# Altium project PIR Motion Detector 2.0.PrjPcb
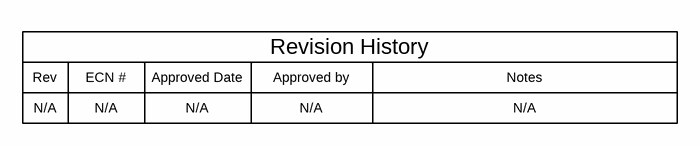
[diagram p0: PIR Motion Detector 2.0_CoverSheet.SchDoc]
CopyrightYear: 2016; PCB_Layout: Krypton Solutions; PCB_Rev: E1; PRJ_Customer: Public Release; PRJ_Engineer: Bilal Malik; PRJ_Number: TIDA-01069; PRJ_Title: Adv Motion Detector Using PIR Sensors; SCH_Rev: E1; TechSupport: http://www.ti.com/support; TID: 01069
4 sheets, 139 parts. Net scope: global (net labels, ports and power ports of the same name join across sheets).
Board file: PIR Motion Detector 2.0_PCB.PcbDoc
Sheets:
  PIR Motion Detector 2.0_CoverSheet.SchDoc
  PIR Motion Detector 2.0_BlankSheet.SchDoc
  PIR Motion Detector 2.0_PowerSheet.SchDoc
  PIR Motion Detector 2.0_EVM_Hardware.SchDoc

## Sheet PIR Motion Detector 2.0_CoverSheet.SchDoc: Cover Sheet
size 431 x 279 mm; Date: Not shown in title block; ApprovedBy: Not shown in title block; CheckedBy: Not shown in title block; Author: Not shown in title block; CompanyName: Not shown in title block; DrawnBy: Bilal Malik; Engineer: Not shown in title block; Organization: Not shown in title block; Address1: Not shown in title block; Address2: Not shown in title block; Address3: Not shown in title block; Address4: Not shown in title block; DocumentNumber: 1; Revision: Use project parameter SCH_Rev; SheetNumber: 1; SheetTotal: 4; PageSetup: Record=PageOptions¦CenterHorizontal=True¦CenterVertical=True¦PrintScale=1.00¦XCorrection=1.00¦YCorrection=1.00¦PrintKind=0¦BorderSize=5000000¦LeftOffset=0¦BottomOffset=0¦Orientation=2¦PaperLength=1000¦PaperWidth=1000¦Scale=100¦PaperSource=15¦PrintQuality=600¦MediaType=1¦DitherType=10¦PaperKind=Letter¦PrintScaleMode=1

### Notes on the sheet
- Rev
- N/A
- ECN #
- Approved Date
- Approved by
- Revision History
- Notes

## Sheet PIR Motion Detector 2.0_BlankSheet.SchDoc: PIR Motion Detector 2.0
size 431 x 279 mm; Date: Not shown in title block; ApprovedBy: Not shown in title block; CheckedBy: Not shown in title block; Author: Not shown in title block; CompanyName: Not shown in title block; DrawnBy: Bilal Malik; Engineer: Not shown in title block; Organization: Not shown in title block; Address1: Not shown in title block; Address2: Not shown in title block; Address3: Not shown in title block; Address4: Not shown in title block; DocumentNumber: 2; Revision: Use project parameter SCH_Rev; SheetNumber: 2; SheetTotal: 4; PageSetup: Record=PageOptions¦CenterHorizontal=True¦CenterVertical=True¦PrintScale=1.00¦XCorrection=1.00¦YCorrection=1.00¦PrintKind=0¦BorderSize=5000000¦LeftOffset=0¦BottomOffset=0¦Orientation=2¦PaperLength=1000¦PaperWidth=1000¦Scale=100¦PaperSource=15¦PrintQuality=600¦MediaType=1¦DitherType=10¦PaperKind=Letter¦PrintScaleMode=1
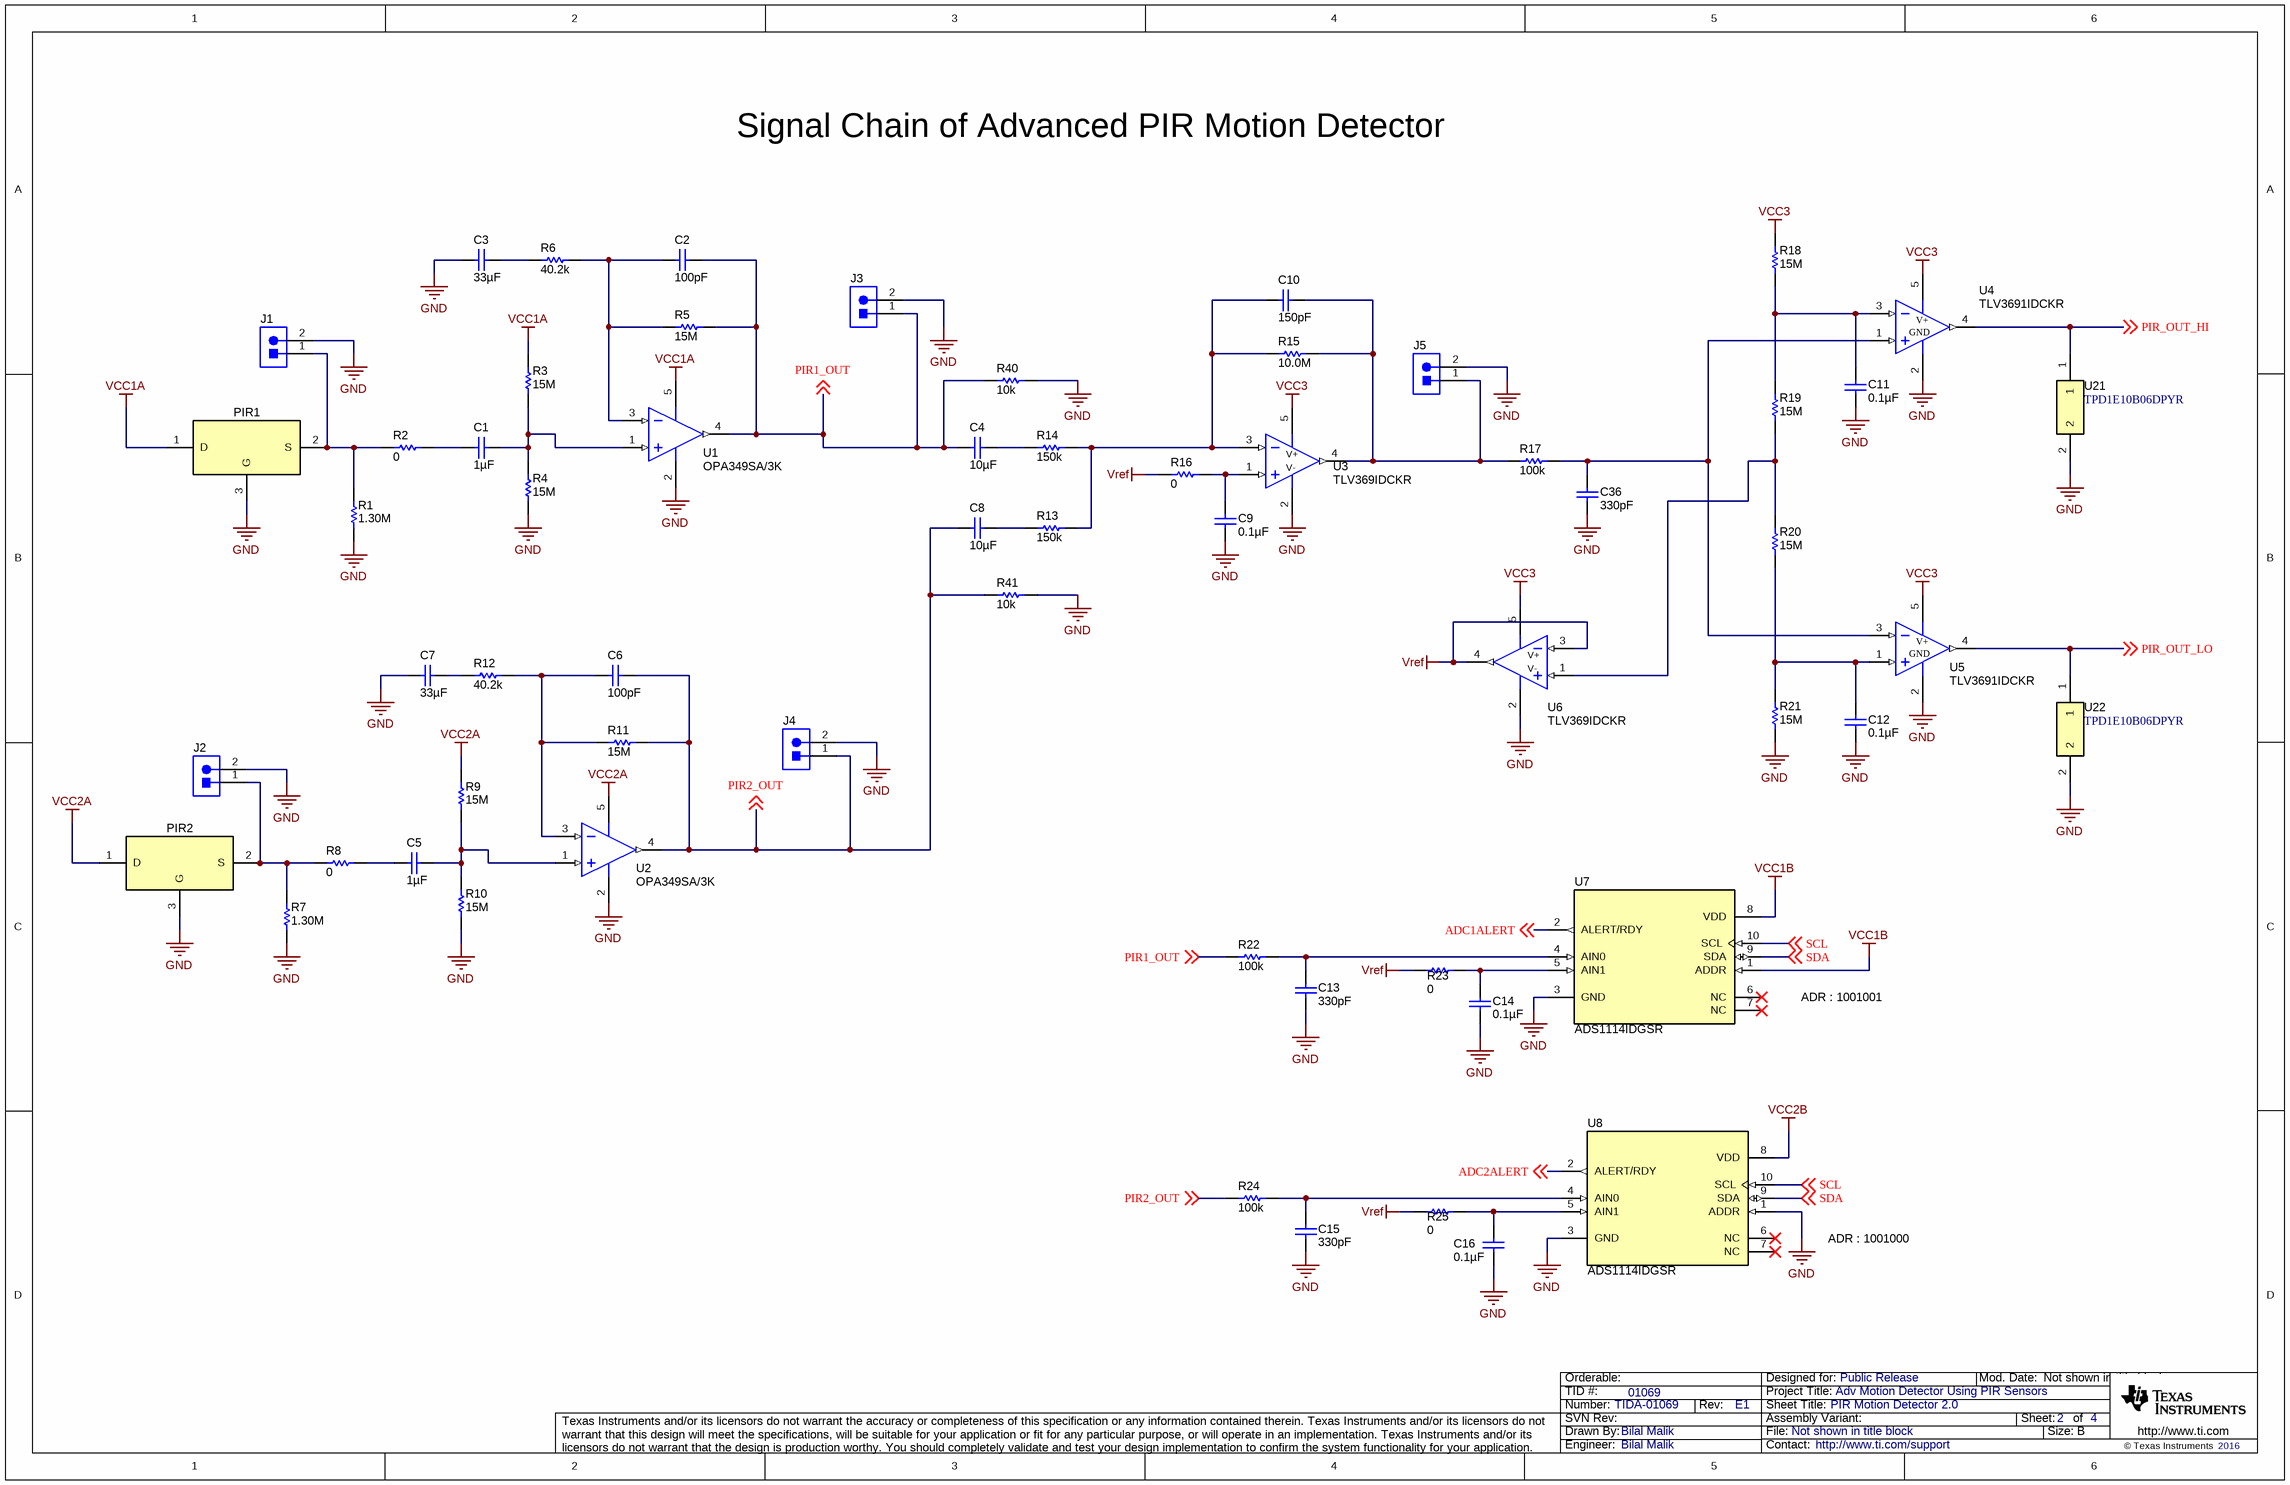
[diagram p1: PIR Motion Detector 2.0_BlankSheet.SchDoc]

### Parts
C1  ValueDisplayed: 1µF  [0402]  (hidden comment: C1005X5R1A105K050BB)
C2  ValueDisplayed: 100pF  [0603]  (hidden comment: 06035A101FAT2A)
C3  ValueDisplayed: 33µF  [0805_HV]  (hidden comment: C2012X5R1A336M125AC)
C4  ValueDisplayed: 10µF  [0603]  (hidden comment: GRM188R61A106ME69D)
C5  ValueDisplayed: 1µF  [0402]  (hidden comment: C1005X5R1A105K050BB)
C6  ValueDisplayed: 100pF  [0603]  (hidden comment: 06035A101FAT2A)
C7  ValueDisplayed: 33µF  [0805_HV]  (hidden comment: C2012X5R1A336M125AC)
C8  ValueDisplayed: 10µF  [0603]  (hidden comment: GRM188R61A106ME69D)
C9  ValueDisplayed: 0.1µF  [0402]  (hidden comment: C1005X7R1H104K050BB)
C10  ValueDisplayed: 150pF  [0603]  (hidden comment: GRM1885C1H151JA01D)
C11  ValueDisplayed: 0.1µF  [0402]  (hidden comment: C1005X7R1H104K050BB)
C12  ValueDisplayed: 0.1µF  [0402]  (hidden comment: C1005X7R1H104K050BB)
C13  ValueDisplayed: 330pF  [0402]  (hidden comment: GRM1555C1H331FA01J)
C14  ValueDisplayed: 0.1µF  [0402]  (hidden comment: C1005X7R1H104K050BB)
C15  ValueDisplayed: 330pF  [0402]  (hidden comment: C1005X5R1A105K050BB)
C16  ValueDisplayed: 0.1µF  [0402]  (hidden comment: C1005X7R1H104K050BB)
C36  ValueDisplayed: 330pF  [0402]  (hidden comment: GRM1555C1H331FA01J)
J1  HMTSW-102-07-G-S-240  [SAMTEC_HMTSW-102-07-G-S-240]  (value not drawn)
J2  HMTSW-102-07-G-S-240  [SAMTEC_HMTSW-102-07-G-S-240]  (value not drawn)
J3  HMTSW-102-07-G-S-240  [SAMTEC_HMTSW-102-07-G-S-240]  (value not drawn)
J4  HMTSW-102-07-G-S-240  [SAMTEC_HMTSW-102-07-G-S-240]  (value not drawn)
J5  HMTSW-102-07-G-S-240  [SAMTEC_HMTSW-102-07-G-S-240]  (value not drawn)
PIR1  IRA-E700ST0  [Murata_IRA-E700ST0]  (value not drawn)
PIR2  IRA-E700ST0  [Murata_IRA-E700ST0]  (value not drawn)
R1  ValueDisplayed: 1.30M  [0402]  (hidden comment: CRCW04021M30FKED)
R2  ValueDisplayed: 0  [0402]  (hidden comment: CRCW04020000Z0ED)
R3  ValueDisplayed: 15M  [0805_HV]  (hidden comment: RMCF0805JT15M0)
R4  ValueDisplayed: 15M  [0805L]  (hidden comment: RMCF0805JT15M0)
R5  ValueDisplayed: 15M  [0805_HV]  (hidden comment: RMCF0805JT15M0)
R6  ValueDisplayed: 40.2k  [0402]  (hidden comment: CRCW040240K2FKED)
R7  ValueDisplayed: 1.30M  [0402]  (hidden comment: CRCW04021M30FKED)
R8  ValueDisplayed: 0  [0402]  (hidden comment: CRCW04020000Z0ED)
R9  ValueDisplayed: 15M  [0805_HV]  (hidden comment: RMCF0805JT15M0)
R10  ValueDisplayed: 15M  [0805L]  (hidden comment: RMCF0805JT15M0)
R11  ValueDisplayed: 15M  [0805_HV]  (hidden comment: RMCF0805JT15M0)
R12  ValueDisplayed: 40.2k  [0402]  (hidden comment: CRCW040240K2FKED)
R13  ValueDisplayed: 150k  [0402]  (hidden comment: CRCW0402150KFKED)
R14  ValueDisplayed: 150k  [0402]  (hidden comment: CRCW0402150KFKED)
R15  ValueDisplayed: 10.0M  [0805_HV]  (hidden comment: CRCW080510M0FKEA)
R16  ValueDisplayed: 0  [0402]  (hidden comment: CRCW04020000Z0ED)
R17  ValueDisplayed: 100k  [0402]  (hidden comment: CRCW0402100KFKED)
R18  ValueDisplayed: 15M  [0805_HV]  (hidden comment: RMCF0805JT15M0)
R19  ValueDisplayed: 15M  [0805_HV]  (hidden comment: RMCF0805JT15M0)
R20  ValueDisplayed: 15M  [0805_HV]  (hidden comment: RMCF0805JT15M0)
R21  ValueDisplayed: 15M  [0805_HV]  (hidden comment: RMCF0805JT15M0)
R22  ValueDisplayed: 100k  [0402]  (hidden comment: CRCW0402100KFKED)
R23  ValueDisplayed: 0  [0402]  (hidden comment: CRCW04020000Z0ED)
R24  ValueDisplayed: 100k  [0402]  (hidden comment: CRCW04020000Z0ED)
R25  ValueDisplayed: 0  [0402]  (hidden comment: CRCW04020000Z0ED)
R40  ValueDisplayed: 10k  [0402]  (hidden comment: CRCW040210K0JNED)
R41  ValueDisplayed: 10k  [0402]  (hidden comment: CRCW040210K0JNED)
U1  OPA349SA/3K  [DCK0005A_N]
U2  OPA349SA/3K  [DCK0005A_N]
U3  TLV369IDCKR  [DCK0005A_N]
U4  TLV3691IDCKR  [DCK0005A_N]
U5  TLV3691IDCKR  [DCK0005A_N]
U6  TLV369IDCKR  [DCK0005A_N]
U7  ADS1114IDGSR  [DGS0010A_N]
U8  ADS1114IDGSR  [DGS0010A_N]
U21  TPD1E10B06DPYR  [DPY0002A]
U22  TPD1E10B06DPYR  [DPY0002A]

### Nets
GND: C3.1 C7.1 C9.2 C11.2 C12.2 C13.2 C14.2 C15.2 C16.2 C36.2 J1.2 J2.2 J3.2 J4.2 J5.2 PIR1.3(G) PIR2.3(G) R1.1 R4.1 R7.1 R10.1 R21.1 R40.1 R41.1 U1.2(V-) U2.2(V-) U3.2(V-) U4.2(GND) U5.2(GND) U6.2(V-) U7.3(GND) U8.1(ADDR) U8.3(GND) U21.2 U22.2
VCC1A: PIR1.1(D) R3.2 U1.5(V+)
VCC1B: U7.1(ADDR) U7.8(VDD)
VCC2A: PIR2.1(D) R9.2 U2.5(V+)
VCC2B: U8.8(VDD)
VCC3: R18.2 U3.5(V+) U4.5(V+) U5.5(V+) U6.5(V+)
Vref: R16.1 R23.1 R25.1 U6.3(IN-) U6.4(OUT)
ADC1ALERT: U7.2(ALERT/RDY) ; off-sheet ADC1ALERT
ADC2ALERT: U8.2(ALERT/RDY) ; off-sheet ADC2ALERT
PIR1_OUT: C2.1 C4.2 J3.1 R5.2 R22.1 R40.2 U1.4(OUT) ; off-sheet PIR1_OUT
PIR2_OUT: C6.1 C8.2 J4.1 R11.2 R24.1 R41.2 U2.4(OUT) ; off-sheet PIR2_OUT
PIR_OUT_HI: U4.4(OUT) U21.1 ; off-sheet PIR_OUT_HI
PIR_OUT_LO: U5.4(OUT) U22.1 ; off-sheet PIR_OUT_LO
SCL: U7.10(SCL) U8.10(SCL) ; off-sheet SCL
SDA: U7.9(SDA) U8.9(SDA) ; off-sheet SDA
NetC1_1: C1.1 R3.1 R4.2 U1.1(IN+)
NetC1_2: C1.2 R2.2
NetC2_2: C2.2 R5.1 R6.2 U1.3(IN-)
NetC3_2: C3.2 R6.1
NetC4_1: C4.1 R14.1
NetC5_1: C5.1 R9.1 R10.2 U2.1(IN+)
NetC5_2: C5.2 R8.2
NetC6_2: C6.2 R11.1 R12.2 U2.3(IN-)
NetC7_2: C7.2 R12.1
NetC8_1: C8.1 R13.1
NetC9_1: C9.1 R16.2 U3.1(IN+)
NetC10_1: C10.1 J5.1 R15.2 R17.1 U3.4(OUT)
NetC10_2: C10.2 R13.2 R14.2 R15.1 U3.3(IN-)
NetC11_1: C11.1 R18.1 R19.2 U4.3(IN-)
NetC12_1: C12.1 R20.1 R21.2 U5.1(IN+)
NetC13_1: C13.1 R22.2 U7.4(AIN0)
NetC14_1: C14.1 R23.2 U7.5(AIN1)
NetC15_1: C15.1 R24.2 U8.4(AIN0)
NetC16_1: C16.1 R25.2 U8.5(AIN1)
NetC36_1: C36.1 R17.2 U4.1(IN+) U5.3(IN-)
NetJ1_1: J1.1 PIR1.2(S) R1.2 R2.1
NetJ2_1: J2.1 PIR2.2(S) R7.2 R8.1
NetR19_1: R19.1 R20.2 U6.1(IN+)

Not connected (* = marked no-connect by the designer): U7 6(NC)* 7(NC)*; U8 6(NC)* 7(NC)*

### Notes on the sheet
- Signal Chain of Advanced PIR Motion Detector
- ADR : 1001001
- ADR : 1001000

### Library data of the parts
C1 C5 = C1005X5R1A105K050BB: CAP, CERM, 1 µF, 10 V, +/- 10%, X5R, 0402; Manufacturer: TDK; Polarized: N; CompType: Capacitor; Value: 1uF; U/M: EA; Cap_F: 0.000001; Tolerance_%: 10; Value1: Unknown; Value2: 10V; TaMin_C: -55; TaMax_C: 85; SizeArea_mm2: 0.5; SizeAreaWB_mm2: 3; SizeX_mm: 1; SizeZ_mm: 0.6; AEC Category: Q200
C2 C6 = 06035A101FAT2A: CAP, CERM, 100 pF, 50 V, +/- 1%, C0G/NP0, 0603; Manufacturer: AVX; Polarized: N; CompType: Capacitor; Value: 100pF; U/M: EA; Cap_F: 0.0000000001; Tolerance_%: 1; Value1: Unknown; VDC_V: 50; Value2: 50V; TaMin_C: -55; TaMax_C: 125; SizeArea_mm2: 1.28; SizeAreaWB_mm2: 4.68; SizeX_mm: 1.6; SizeY_mm: 0.8; AEC Category: Q200
C3 C7 = C2012X5R1A336M125AC: CAP, CERM, 33 µF, 10 V, +/- 20%, X5R, 0805; Manufacturer: TDK; Polarized: N; CompType: Capacitor; Value: 33uF; U/M: EA; Cap_F: 0.000033; Tolerance_%: 20; ESR_ohm: 0.001694; Value1: 0.001694 ohm; VDC_V: 10; Value2: 10V; IRMS_A: 5.01281; TaMin_C: -55; TaMax_C: 85; Cap_Case: 0805; SizeArea_mm2: 2.5; SizeAreaWB_mm2: 6.75; SizeX_mm: 2; SizeY_mm: 1.25; SizeZ_mm: 1.45; AEC Category: Q200
C4 C8 = GRM188R61A106ME69D: CAP, CERM, 10 µF, 10 V, +/- 20%, X5R, 0603; Manufacturer: MuRata; Polarized: N; CompType: Capacitor; Value: 10uF; U/M: EA; Cap_F: 0.00001; Tolerance_%: 20; Value1: Unknown; VDC_V: 10; Value2: 10V; TaMin_C: -55; TaMax_C: 85; SizeArea_mm2: 1.28; SizeAreaWB_mm2: 4.68; SizeX_mm: 1.6; SizeY_mm: 0.8; SizeZ_mm: 1; AEC Category: Q200
C9 C11 C12 C14 C16 = C1005X7R1H104K050BB: CAP, CERM, 0.1 µF, 50 V, +/- 10%, X7R, 0402; Manufacturer: TDK; Polarized: N; CompType: Capacitor; Value: 0.1uF; U/M: EA; Cap_F: 0.0000001; Tolerance_%: 10; ESR_ohm: 0.039064; Value1: 0.039064 ohm; VDC_V: 50; Value2: 50V; IRMS_A: 0.814669; TaMin_C: -55; TaMax_C: 125; SizeArea_mm2: 0.5; SizeAreaWB_mm2: 3; SizeX_mm: 1; SizeZ_mm: 0.6; AEC Category: Q200
C10 = GRM1885C1H151JA01D: CAP, CERM, 150 pF, 50 V, +/- 5%, C0G/NP0, 0603; Manufacturer: MuRata; Polarized: N; CompType: Capacitor; Value: 150pF; U/M: EA; Cap_F: 0.00000000015; Tolerance_%: 5; Value1: Unknown; VDC_V: 50; Value2: 50V; TaMin_C: -55; TaMax_C: 125; SizeArea_mm2: 1.28; SizeAreaWB_mm2: 4.68; SizeX_mm: 1.6; SizeY_mm: 0.8; SizeZ_mm: 1; AEC Category: Q200
C13 C15 C36 = GRM1555C1H331FA01J: CAP, CERM, 330 pF, 50 V, +/- 1%, C0G/NP0, 0402; Manufacturer: MuRata; Polarized: N; CompType: Capacitor; Value: 330pF; U/M: EA; Cap_F: 0.00000000033; Tolerance_%: 1; Value1: Unknown; VDC_V: 50; Value2: 50V; TaMin_C: -55; TaMax_C: 125; SizeArea_mm2: 0.5; SizeAreaWB_mm2: 3; SizeZ_mm: 0.6; AEC Category: Q200
J1-J5 = HMTSW-102-07-G-S-240: Header, 100mil, 2x1, Gold, TH; Manufacturer: Samtec; SymbolCreator: a0412235
PIR1 PIR2 = IRA-E700ST0: Pyroelectric Infrared Sensor, TH; Manufacturer: MuRata; SymbolCreator: Altium; SizeAreaWB_mm2: 125.44; SizeArea_mm2: 84.64; SizeX_mm: 9.2; SizeZ_mm: 4.9
R1 R7 = CRCW04021M30FKED: RES, 1.30 M, 1%, 0.063 W, 0402; Manufacturer: Vishay-Dale; CompType: Resistor; Value: 1.30Meg; Res_ohm: 1300000; Value_Code: 1M30; Tolerance_%: 1; Power_W: 0.063; Value2: 0.063W; VDC_V: 50; TempCo: 100 ppm/C; SizeArea_mm2: 0.5; SizeZ_mm: 0.6; EIA_Code: E96; U/M: EA; AEC Category: Q200
R2 R8 R16 R23 R25 = CRCW04020000Z0ED: RES, 0, 5%, 0.063 W, 0402; Manufacturer: Vishay-Dale; CompType: Resistor; Value: 0; Value_Code: 0000; Tolerance_%: 5; Power_W: 0.063; Value2: 0.063W; VDC_V: 50; TempCo: 200 ppm/C; SizeArea_mm2: 0.5; SizeX_mm: 1; SizeZ_mm: 0.6; EIA_Code: E24; U/M: EA; AEC Category: Q200
R3-R5 R9-R11 R18-R21 = RMCF0805JT15M0: RES, 15 M, 5%, 0.125 W, AEC-Q200 Grade 0, 0805; Manufacturer: Stackpole Electronics Inc; CompType: Resistor; Value: 15Meg; Res_ohm: 15000000; Value_Code: 15M0; Tolerance_%: 5; Power_W: 0.125; Value2: 0.125W; VDC_V: 75; TempCo: 200 ppm/C; SizeArea_mm2: 2.5; SizeX_mm: 2; SizeY_mm: 1.25; SizeZ_mm: 1.45; U/M: EA; AEC Category: Q200; AEC Qualified: Y; AEC Grade: 0
R6 R12 = CRCW040240K2FKED: RES, 40.2 k, 1%, 0.063 W, 0402; Manufacturer: Vishay-Dale; CompType: Resistor; Value: 40.2k; Res_ohm: 40200; Value_Code: 40k2; Tolerance_%: 1; Power_W: 0.063; Value2: 0.063W; VDC_V: 50; TempCo: 100 ppm/C; SizeArea_mm2: 0.5; SizeZ_mm: 0.6; EIA_Code: E96; U/M: EA; AEC Category: Q200
R13 R14 = CRCW0402150KFKED: RES, 150 k, 1%, 0.063 W, 0402; Manufacturer: Vishay-Dale; CompType: Resistor; Value: 150k; Res_ohm: 150000; Tolerance_%: 1; Power_W: 0.063; Value2: 0.063W; VDC_V: 50; TempCo: 100 ppm/C; SizeArea_mm2: 0.5; SizeZ_mm: 0.6; EIA_Code: E96; U/M: EA; AEC Category: Q200
R15 = CRCW080510M0FKEA: RES, 10.0 M, 1%, 0.125 W, 0805; Manufacturer: Vishay-Dale; CompType: Resistor; Value: 10.0Meg; Res_ohm: 10000000; Value_Code: 10M0; Tolerance_%: 1; Power_W: 0.125; Value2: 0.125W; VDC_V: 150; TempCo: 100 ppm/C; SizeArea_mm2: 2.5; SizeX_mm: 2; SizeY_mm: 1.25; SizeZ_mm: 1.45; EIA_Code: E96; U/M: EA; AEC Category: Q200
R17 R22 R24 = CRCW0402100KFKED: RES, 100 k, 1%, 0.063 W, 0402; Manufacturer: Vishay-Dale; CompType: Resistor; Value: 100k; Res_ohm: 100000; Tolerance_%: 1; Power_W: 0.063; Value2: 0.063W; VDC_V: 50; TempCo: 100 ppm/C; SizeArea_mm2: 0.5; SizeZ_mm: 0.6; EIA_Code: E96; U/M: EA; AEC Category: Q200
R40 R41 = CRCW040210K0JNED: RES, 10 k, 5%, 0.063 W, 0402; Manufacturer: Vishay-Dale; CompType: Resistor; Value: 10k; Res_ohm: 10000; Value_Code: 10k0; Tolerance_%: 5; Power_W: 0.063; Value2: 0.063W; VDC_V: 50; TempCo: 200 ppm/C; SizeArea_mm2: 0.5; SizeX_mm: 1; SizeZ_mm: 0.6; EIA_Code: E24; U/M: EA; AEC Category: Q200
U1 U2 = OPA349SA/3K: 1 uA, Rail-to-Rail, CMOS Operational Amplifier, 1.8 to 5.5 V, 0 to 85 degC, 5-pin SOT23 (DCK0005A), Green (RoHS & no Sb/Br); Manufacturer: Texas Instruments; Alternate PartNumber: Equivalent; CMRR(Min)(dB): 48; GBW(Typ)(MHz): 0.07; IIB(Max)(pA): 10; Iq per channel(Max)(mA): 0.002; Number of Channels: 1; Offset Drift(Typ)(uV/C): 15; Packing: LARGE T&R; Rating: Catalog; Slew Rate(Typ)(V/us): 0.02; Sub Family: Low Input Bias Current Amp (<=10pA), Low Power Amp (<=500uA), Low Supply Voltage Amplifier (<=2.7V), Precision Amplifier; Total Supply Voltage(Max)(+5V is 5, +/-5V is 10): 5.5; Total Supply Voltage(Min)(+5V is 5, +/-5V is 10): 1.8
U3 U6 = TLV369IDCKR: Cost-Optimized, 800-nA, 1.8-V, Rail-to-Rail I/O Operational Amplifier with Zero-Crossover Distortion, DCK0005A (SOT-5); Alternate PartNumber: TLV369IDCKT; Manufacturer: Texas Instruments; SymbolCreator: a0411595; SizeArea_mm2: 4.2; SizeAreaWB_mm2: 9.3; SizeX_mm: 2.1; SizeY_mm: 2; SizeZ_mm: 1.1; CompType: IC; U/M: EA
U4 U5 = TLV3691IDCKR: 0.9-V to 6.5-V, Nanopower Comparator, DCK0005A (SOT-5); Alternate PartNumber: TLV3691IDCKT; Manufacturer: Texas Instruments; SymbolCreator: OpAmp IC; SizeArea_mm2: 4.2; SizeAreaWB_mm2: 9.3; SizeX_mm: 2.1; SizeY_mm: 2; SizeZ_mm: 1.1; CompType: IC; U/M: EA
U7 U8 = ADS1114IDGSR: Ultra-Small, Low-Power, I2C-Compatible, 860-SPS, 16-Bit ADCs With Internal Reference, Oscillator, and Programmable Comparator, DGS0010A (VSSOP-10); Alternate PartNumber: ADS1114IDGST; Manufacturer: Texas Instruments; SymbolCreator: a0411947; SizeArea_mm2: 14.7; SizeAreaWB_mm2: 23.6; SizeX_mm: 4.9; SizeY_mm: 3; SizeZ_mm: 1.1; CompType: IC; U/M: EA
U21 U22 = TPD1E10B06DPYR: ESD in 0402 Package with 10 pF Capacitance and 6 V Breakdown, 1 Channel, -40 to +125 degC, 2-pin X2SON (DPY), Green (RoHS & no Sb/Br); Manufacturer: Texas Instruments; Alternate PartNumber: Equivalent; Breakdown Voltage(Min)(V): 6; Eco-Plan: TBD; IEC 61000-4-2 Air-Gap(+/- kV): 30; IO Capacitance(Typ)(pF): 10; SubFamily: ESD Solution

## Sheet PIR Motion Detector 2.0_PowerSheet.SchDoc: Sensors & Booster Pack
size 431 x 279 mm; Date: Not shown in title block; ApprovedBy: Not shown in title block; CheckedBy: Not shown in title block; Author: Not shown in title block; CompanyName: Not shown in title block; DrawnBy: Bilal Malik; Engineer: Not shown in title block; Organization: Not shown in title block; Address1: Not shown in title block; Address2: Not shown in title block; Address3: Not shown in title block; Address4: Not shown in title block; DocumentNumber: 3; Revision: Use project parameter SCH_Rev; SheetNumber: 3; SheetTotal: 4; PageSetup: Record=PageOptions¦CenterHorizontal=True¦CenterVertical=True¦PrintScale=1.00¦XCorrection=1.00¦YCorrection=1.00¦PrintKind=0¦BorderSize=5000000¦LeftOffset=0¦BottomOffset=0¦Orientation=2¦PaperLength=1000¦PaperWidth=1000¦Scale=100¦PaperSource=15¦PrintQuality=-3¦MediaType=1¦DitherType=10¦PrintScaleMode=1¦PaperKind=Letter
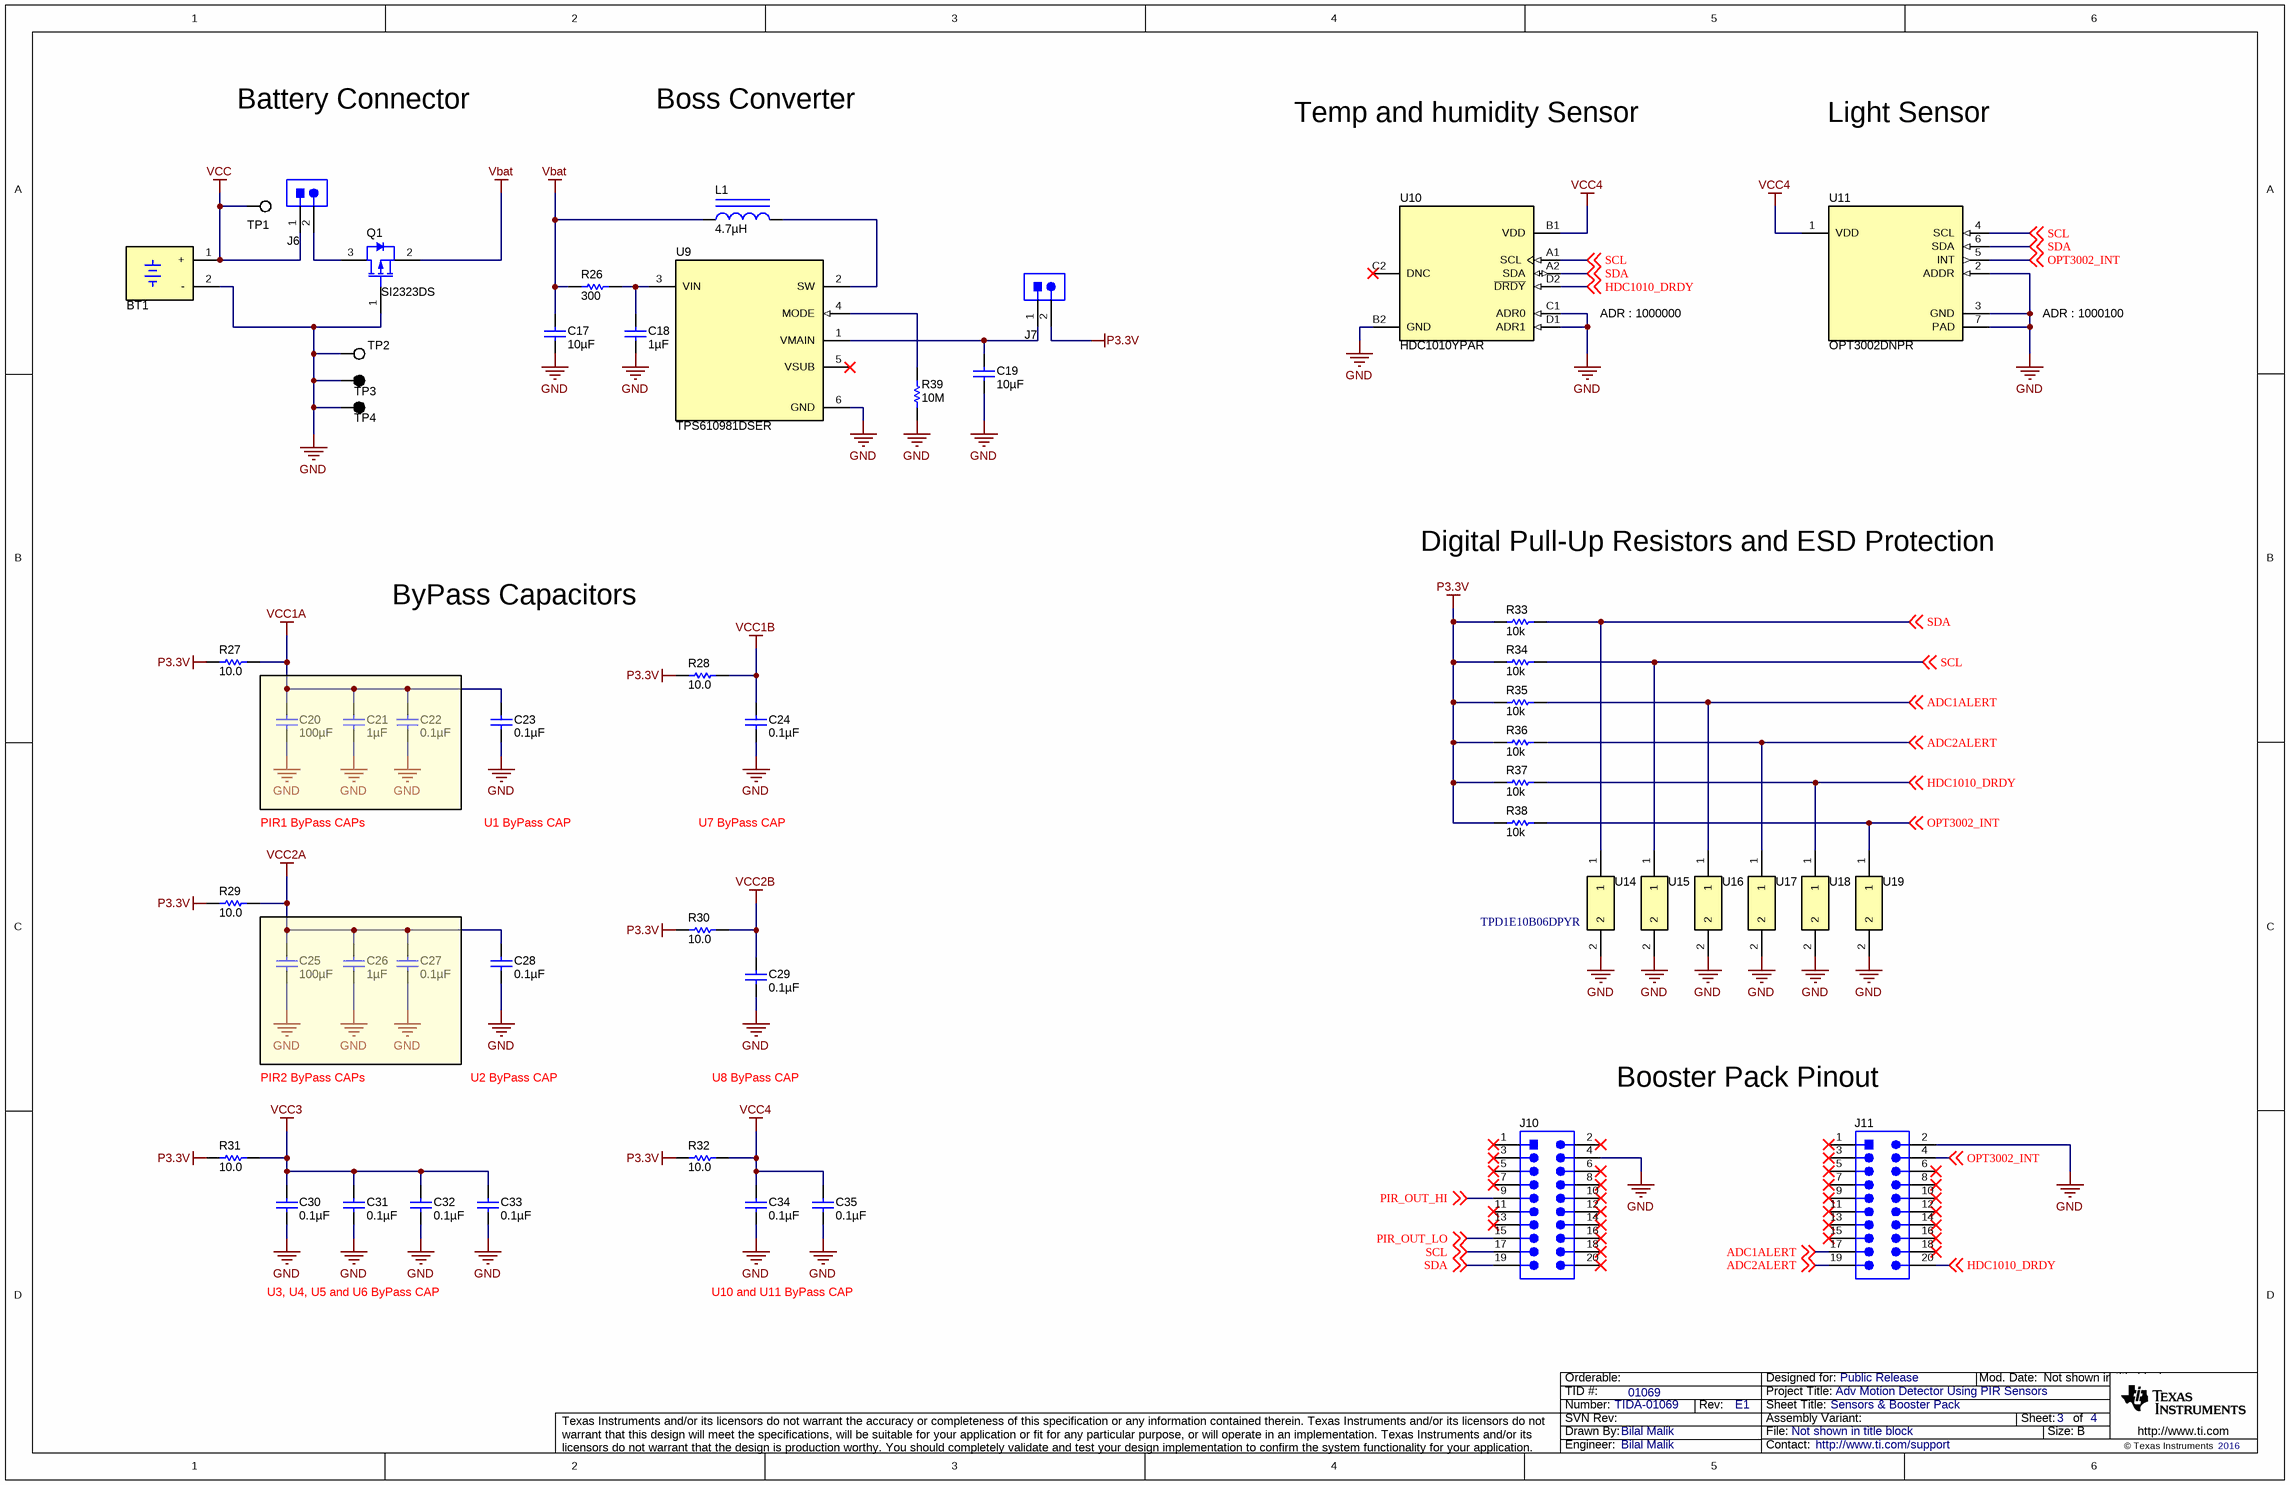
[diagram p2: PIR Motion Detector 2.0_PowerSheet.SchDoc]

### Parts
BT1  2466  [Keystone_2466]  (value not drawn)
C17  ValueDisplayed: 10µF  [0603]  (hidden comment: GRM188R60J106ME47D)
C18  ValueDisplayed: 1µF  [0402]  (hidden comment: GRM1555C1H331FA01J)
C19  ValueDisplayed: 10µF  [0402_070]  (hidden comment: GRM155R60G106ME44D)
C20  ValueDisplayed: 100µF  [1206_190]  (hidden comment: C3216X5R1A107M160AC)
C21  ValueDisplayed: 1µF  [0603]  (hidden comment: 06033C105KAT2A)
C22  ValueDisplayed: 0.1µF  [0402]  (hidden comment: 0402YC104KAT2A)
C23  ValueDisplayed: 0.1µF  [0402]  (hidden comment: 0402YC104KAT2A)
C24  ValueDisplayed: 0.1µF  [0402]  (hidden comment: 0402YC104KAT2A)
C25  ValueDisplayed: 100µF  [1206_190]  (hidden comment: C3216X5R1A107M160AC)
C26  ValueDisplayed: 1µF  [0603]  (hidden comment: 06033C105KAT2A)
C27  ValueDisplayed: 0.1µF  [0402]  (hidden comment: 0402YC104KAT2A)
C28  ValueDisplayed: 0.1µF  [0402]  (hidden comment: 0402YC104KAT2A)
C29  ValueDisplayed: 0.1µF  [0402]  (hidden comment: 0402YC104KAT2A)
C30  ValueDisplayed: 0.1µF  [0402]  (hidden comment: 0402YC104KAT2A)
C31  ValueDisplayed: 0.1µF  [0402]  (hidden comment: 0402YC104KAT2A)
C32  ValueDisplayed: 0.1µF  [0402]  (hidden comment: 0402YC104KAT2A)
C33  ValueDisplayed: 0.1µF  [0402]  (hidden comment: 0402YC104KAT2A)
C34  ValueDisplayed: 0.1µF  [0402]  (hidden comment: 0402YC104KAT2A)
C35  ValueDisplayed: 0.1µF  [0402]  (hidden comment: 0402YC104KAT2A)
J6  87898-0204  [Molex_87898-0204]  (value not drawn)
J7  87898-0204  [Molex_87898-0204]  (value not drawn)
J10  PEC10DAAN  [SULLINS_PEC10DAAN]  (value not drawn)
J11  PEC10DAAN  [SULLINS_PEC10DAAN]  (value not drawn)
L1  ValueDisplayed: 4.7µH  [VLF302510MT]  (hidden comment: VLF302510MT-4R7M)
Q1  SI2323DS  [SOT-23]
R26  ValueDisplayed: 300  [0402]  (hidden comment: CRCW04020000Z0ED)
R27  ValueDisplayed: 10.0  [0402]  (hidden comment: CRCW040210R0FKED)
R28  ValueDisplayed: 10.0  [0402]  (hidden comment: CRCW040210R0FKED)
R29  ValueDisplayed: 10.0  [0402]  (hidden comment: CRCW040210R0FKED)
R30  ValueDisplayed: 10.0  [0402]  (hidden comment: CRCW040210R0FKED)
R31  ValueDisplayed: 10.0  [0402]  (hidden comment: CRCW040210R0FKED)
R32  ValueDisplayed: 10.0  [0402]  (hidden comment: CRCW040210R0FKED)
R33  ValueDisplayed: 10k  [0402]  (hidden comment: CRCW040210K0JNED)
R34  ValueDisplayed: 10k  [0402]  (hidden comment: CRCW040210K0JNED)
R35  ValueDisplayed: 10k  [0402]  (hidden comment: CRCW040210K0JNED)
R36  ValueDisplayed: 10k  [0402]  (hidden comment: CRCW040210K0JNED)
R37  ValueDisplayed: 10k  [0402]  (hidden comment: CRCW040210K0JNED)
R38  ValueDisplayed: 10k  [0402]  (hidden comment: CRCW040210K0JNED)
R39  ValueDisplayed: 10M  [0603]  (hidden comment: CRCW060310M0JNEA)
TP1  5015  [Testpoint_Keystone_Miniature]  (value not drawn)
TP2  5015  [Testpoint_Keystone_Miniature]  (value not drawn)
TP3  5001  [Keystone5001]  (value not drawn)
TP4  5001  [Keystone5001]  (value not drawn)
U9  TPS610981DSER  [DSE0006A]
U10  HDC1010YPAR  [YPA0008AGAE]
U11  OPT3002DNPR  [DNP0006A]
U14  TPD1E10B06DPYR  [DPY0002A]
U15  TPD1E10B06DPYR  [DPY0002A]  (value not drawn)
U16  TPD1E10B06DPYR  [DPY0002A]  (value not drawn)
U17  TPD1E10B06DPYR  [DPY0002A]  (value not drawn)
U18  TPD1E10B06DPYR  [DPY0002A]  (value not drawn)
U19  TPD1E10B06DPYR  [DPY0002A]  (value not drawn)

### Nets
GND: BT1.2(-) C17.2 C18.2 C19.2 C20.2 C21.2 C22.2 C23.2 C24.2 C25.2 C26.2 C27.2 C28.2 C29.2 C30.2 C31.2 C32.2 C33.2 C34.2 C35.2 J10.4 J11.2 Q1.1(G) R39.1 TP2.1 TP3.1 TP4.1 U9.6(GND) U10.B2(GND) U10.C1(ADR0) U10.D1(ADR1) U11.2(ADDR) U11.3(GND) U11.7(PAD) U14.2 U15.2 U16.2 U17.2 U18.2 U19.2
P3.3V: J7.2 R27.1 R28.1 R29.1 R30.1 R31.1 R32.1 R33.2 R34.2 R35.2 R36.2 R37.2 R38.2
Vbat: C17.1 L1.1 Q1.2(S) R26.1
VCC: BT1.1(+) J6.1 TP1.1
VCC1A: C20.1 C21.1 C22.1 C23.1 R27.2
VCC1B: C24.1 R28.2
VCC2A: C25.1 C26.1 C27.1 C28.1 R29.2
VCC2B: C29.1 R30.2
VCC3: C30.1 C31.1 C32.1 C33.1 R31.2
VCC4: C34.1 C35.1 R32.2 U10.B1(VDD) U11.1(VDD)
ADC1ALERT: J11.17 R35.1 U16.1 ; off-sheet ADC1ALERT
ADC2ALERT: J11.19 R36.1 U17.1 ; off-sheet ADC2ALERT
HDC1010_DRDY: J11.20 R37.1 U10.D2(~{DRDY}) U18.1 ; off-sheet HDC1010_DRDY
OPT3002_INT: J11.4 R38.1 U11.5(INT) U19.1 ; off-sheet OPT3002_INT
PIR_OUT_HI: J10.9 ; off-sheet PIR_OUT_HI
PIR_OUT_LO: J10.15 ; off-sheet PIR_OUT_LO
SCL: J10.17 R34.1 U10.A1(SCL) U11.4(SCL) U15.1 ; off-sheet SCL
SDA: J10.19 R33.1 U10.A2(SDA) U11.6(SDA) U14.1 ; off-sheet SDA
NetC18_1: C18.1 R26.2 U9.3(VIN)
NetC19_1: C19.1 J7.1 U9.1(VMAIN)
NetJ6_2: J6.2 Q1.3(D)
NetL1_2: L1.2 U9.2(SW)
NetR39_2: R39.2 U9.4(MODE)

Not connected (* = marked no-connect by the designer): J10 1* 2* 3* 5* 6* 7* 8* 10* 11* 12* 13* 14* 16* 18* 20*; J11 1* 3* 5* 6* 7* 8* 9* 10* 11* 12* 13* 14* 15* 16* 18*; U9 5(VSUB)*; U10 C2(DNC)*

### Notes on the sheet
- Battery Connector
- Boss Converter
- Temp and humidity Sensor
- Light Sensor
- ADR : 1000000
- ADR : 1000100
- Digital Pull-Up Resistors and ESD Protection
- ByPass Capacitors
- PIR1 ByPass CAPs
- U1 ByPass CAP
- U7 ByPass CAP
- PIR2 ByPass CAPs
- U2 ByPass CAP
- U8 ByPass CAP
- Booster Pack Pinout
- U3, U4, U5 and U6 ByPass CAP
- U10 and U11 ByPass CAP

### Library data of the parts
BT1 = 2466: HOLDER BATTERY AAA, TH; Manufacturer: Keystone; SymbolCreator: a0411947; CompType: Battery Holder
C17 = GRM188R60J106ME47D: CAP, CERM, 10 µF, 6.3 V, +/- 20%, X5R, 0603; Manufacturer: MuRata; Polarized: N; CompType: Capacitor; Value: 10uF; U/M: EA; Cap_F: 0.00001; Tolerance_%: 20; ESR_ohm: 0.009; Value1: 0.009 ohm; VDC_V: 6.3; Value2: 6.3V; IRMS_A: 2.74; TaMin_C: -55; TaMax_C: 125; SizeArea_mm2: 1.28; SizeAreaWB_mm2: 4.68; SizeX_mm: 1.6; SizeY_mm: 0.8; SizeZ_mm: 1; AEC Category: Q200
C18 = GRM155R61A105KE15D: CAP, CERM, 1 µF, 10 V, +/- 10%, X5R, 0402; Manufacturer: MuRata; Polarized: N; CompType: Capacitor; Value: 1uF; U/M: EA; Cap_F: 0.000001; Tolerance_%: 10; Value1: Unknown; Value2: 10V; TaMin_C: -55; TaMax_C: 85; SizeArea_mm2: 0.5; SizeAreaWB_mm2: 3; SizeX_mm: 1; SizeZ_mm: 0.6; AEC Category: Q200
C19 = GRM155R60G106ME44D: CAP, CERM, 10 µF, 4 V, +/- 20%, X5R, 0402; Manufacturer: MuRata; Polarized: N; CompType: Capacitor; Value: 10uF; U/M: EA; Cap_F: 0.00001; Tolerance_%: 20; Value1: Unknown; VDC_V: 4; Value2: 4V; TaMin_C: -55; TaMax_C: 85; Cap_Case: 0402; SizeArea_mm2: 0.5; SizeAreaWB_mm2: 3; SizeX_mm: 1; SizeZ_mm: 0.7; AEC Category: Q200
C20 C25 = C3216X5R1A107M160AC: CAP, CERM, 100 µF, 10 V, +/- 20%, X5R, 1206_190; Manufacturer: TDK; Polarized: N; CompType: Capacitor; Value: 100uF; U/M: EA; Cap_F: 0.0001; Tolerance_%: 20; ESR_ohm: 0.002838; Value1: 0.002838 ohm; VDC_V: 10; Value2: 10V; IRMS_A: 4.30694; TaMin_C: -55; TaMax_C: 85; SizeArea_mm2: 5.12; SizeAreaWB_mm2: 10.92; SizeX_mm: 3.2; SizeY_mm: 1.6; SizeZ_mm: 1.9; AEC Category: Q200
C21 C26 = 06033C105KAT2A: CAP, CERM, 1 µF, 25 V, +/- 10%, X7R, 0603; Manufacturer: AVX; Polarized: N; CompType: Capacitor; Value: 1uF; U/M: EA; Cap_F: 0.000001; Tolerance_%: 10; Value1: Unknown; VDC_V: 25; Value2: 25V; TaMin_C: -55; TaMax_C: 125; SizeArea_mm2: 1.28; SizeAreaWB_mm2: 4.68; SizeX_mm: 1.6; SizeY_mm: 0.8; SizeZ_mm: 1; AEC Category: Q200
C22-C24 C27-C35 = 0402YC104KAT2A: CAP, CERM, 0.1 µF, 16 V, +/- 10%, X7R, 0402; Manufacturer: AVX; Polarized: N; CompType: Capacitor; Value: 0.1uF; U/M: EA; Cap_F: 0.0000001; Tolerance_%: 10; Value1: Unknown; VDC_V: 16; Value2: 16V; TaMin_C: -55; TaMax_C: 125; SizeArea_mm2: 0.5; SizeAreaWB_mm2: 3; SizeX_mm: 1; SizeZ_mm: 0.6; AEC Category: Q200
J6 J7 = 87898-0204: Header, 2.54 mm, 2x1, Gold, R/A, SMT; Manufacturer: Molex; SymbolCreator: a0412235; Pitch_mm: 2.54; Gender: Male; Shrouded: N; Row_Count: 1
J10 J11 = PEC10DAAN: Header, 100mil, 10x2, TH; Manufacturer: Sullins Connector Solutions; SymbolCreator: a0412235
L1 = VLF302510MT-4R7M: Inductor, Shielded, Ferrite, 4.7 µH, 0.86 A, 0.168 ohm, SMD; Manufacturer: TDK; Value: 4.7uH; Ind_H: 4.7E-6; Imax_A: 0.86; Irms: 1.08A @ 40C rise; Isat: 0.86A @ 30% inductance drop; DCR_ohm: 0.168; Value2: 0.86A; SizeAreaWB_mm2: 15.54; SizeArea_mm2: 8.64; SizeX_mm: 2.7; SizeY_mm: 3.2; SizeZ_mm: 1; AEC Category: Q200
Q1 = SI2323DS: MOSFET, P-CH, -20 V, -3.7 A, SOT-23; Manufacturer: Vishay-Siliconix; Alternate Manufacturer: None; U/M: EA; ChType: P; Value: -20V; Value1: 0.031 ohm; Rdson45_ohm: 0.031; Value2: 12.5 nC; QgTyp_nC: 12.5; Vgs_V: -8; SizeAreaWB_mm2: 14; SizeArea_mm2: 7.5; SizeX_mm: 2.5; SizeY_mm: 3; SizeZ_mm: 1.1; AEC Category: Q101
R26 = CRCW0402300RJNED: RES, 300, 5%, 0.063 W, 0402; Manufacturer: Vishay-Dale; CompType: Resistor; Value: 300; Value_Code: 300R; Tolerance_%: 5; Power_W: 0.063; Value2: 0.063W; VDC_V: 50; TempCo: 200 ppm/C; SizeArea_mm2: 0.5; SizeX_mm: 1; SizeZ_mm: 0.6; EIA_Code: E24; U/M: EA; AEC Category: Q200
R27-R32 = CRCW040210R0FKED: RES, 10.0, 1%, 0.063 W, 0402; Manufacturer: Vishay-Dale; CompType: Resistor; Value: 10.0; Res_ohm: 10; Value_Code: 10R0; Tolerance_%: 1; Power_W: 0.063; Value2: 0.063W; VDC_V: 50; TempCo: 100 ppm/C; SizeArea_mm2: 0.5; SizeZ_mm: 0.6; EIA_Code: E96; U/M: EA; AEC Category: Q200
R33-R38 = CRCW040210K0JNED: as R40 on sheet PIR Motion Detector 2.0_BlankSheet
R39 = CRCW060310M0JNEA: RES, 10 M, 5%, 0.1 W, 0603; Manufacturer: Vishay-Dale; CompType: Resistor; Value: 10Meg; Res_ohm: 10000000; Value_Code: 10M0; Tolerance_%: 5; Power_W: 0.1; Value2: 0.1W; VDC_V: 75; TempCo: 200 ppm/C; SizeArea_mm2: 1.28; SizeX_mm: 1.6; SizeY_mm: 0.8; SizeZ_mm: 1; EIA_Code: E24; U/M: EA; AEC Category: Q200
TP1 TP2 = 5015: Test Point, Miniature, SMT; Manufacturer: Keystone; CompType: Test Point Loop
TP3 TP4 = 5001: Test Point, Miniature, Black, TH; Manufacturer: Keystone; CompType: Test Point Loop; ContactFinish: Silver
U9 = TPS610981DSER: Ultra-Low Quiescent Current Synchronous Boost with Integrated LDO/Load Switch, DSE0006A (WSON-6); Alternate PartNumber: TPS610981DSET; Manufacturer: Texas Instruments; SymbolCreator: Altium; SizeArea_mm2: 2.25; SizeAreaWB_mm2: 6.25; SizeX_mm: 1.5; SizeZ_mm: 0.8; CompType: IC; U/M: EA
U10 = HDC1010YPAR: Low Power, High Accuracy Digital Humidity Sensor with Temperature Sensor, YPA0008AGAE (DSBGA-8); Alternate PartNumber: HDC1010YPAT; Manufacturer: Texas Instruments; SymbolCreator: Altium; SizeArea_mm2: 3.2436; SizeAreaWB_mm2: 7.8736; SizeX_mm: 1.59; SizeY_mm: 2.04; SizeZ_mm: 0.675; CompType: IC; U/M: EA
U11 = OPT3002DNPR: OPT3002 Light to Digital Sensor, DNP0006A (USON-6); Alternate PartNumber: OPT3002DNPT; Manufacturer: Texas Instruments; SymbolCreator: a0411947; SizeArea_mm2: 4; SizeAreaWB_mm2: 9; SizeX_mm: 2; SizeZ_mm: 0.65; CompType: IC; U/M: EA
U14-U19 = TPD1E10B06DPYR: as U21 on sheet PIR Motion Detector 2.0_BlankSheet

## Sheet PIR Motion Detector 2.0_EVM_Hardware.SchDoc: Hardware
size 431 x 279 mm; Date: Not shown in title block; ApprovedBy: Not shown in title block; CheckedBy: Not shown in title block; Author: Not shown in title block; CompanyName: Not shown in title block; DrawnBy: Bilal Malik; Engineer: Not shown in title block; Organization: Not shown in title block; Address1: Not shown in title block; Address2: Not shown in title block; Address3: Not shown in title block; Address4: Not shown in title block; DocumentNumber: 4; Revision: Use project parameter SCH_Rev; SheetNumber: 4; SheetTotal: 4; PageSetup: Record=PageOptions¦CenterHorizontal=True¦CenterVertical=True¦PrintScale=1.00¦XCorrection=1.00¦YCorrection=1.00¦PrintKind=0¦BorderSize=5000000¦LeftOffset=0¦BottomOffset=0¦Orientation=2¦PaperLength=1000¦PaperWidth=1000¦Scale=100¦PaperSource=15¦PrintQuality=600¦MediaType=1¦DitherType=10¦PaperKind=Letter¦PrintScaleMode=1
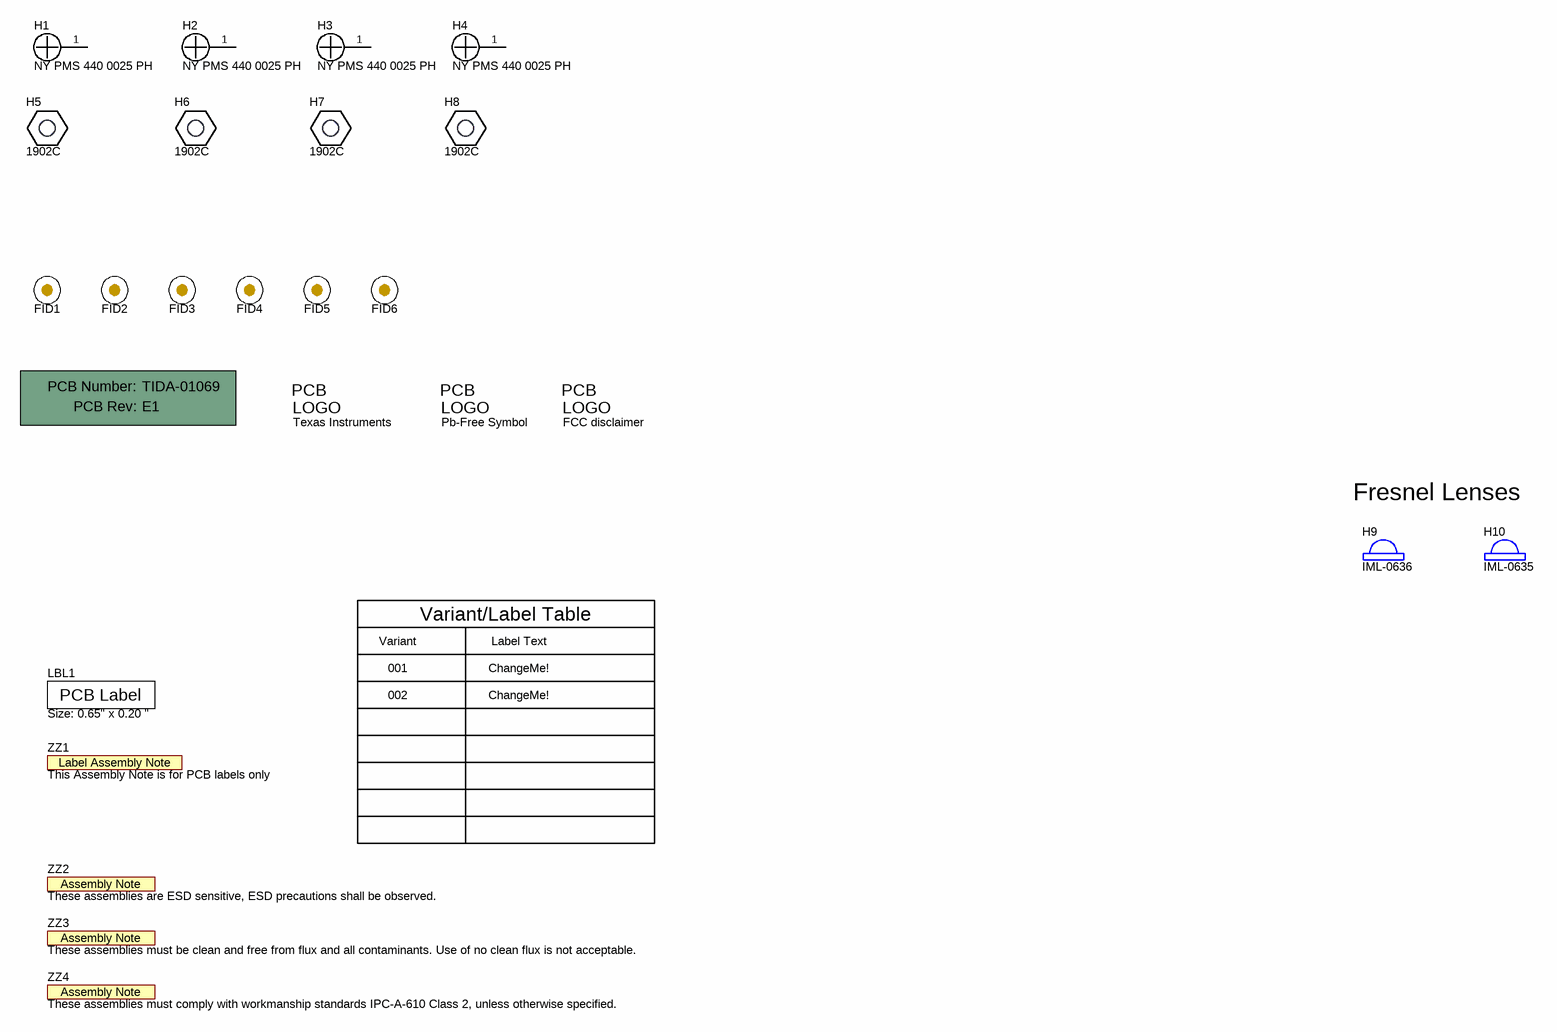
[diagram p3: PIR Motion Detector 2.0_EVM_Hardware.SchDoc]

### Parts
!PCB  Printed Circuit Board  (value not drawn)  (mechanical)
FID1  Fiducial  [Fiducial10-20]  (value not drawn)
FID2  Fiducial  [Fiducial10-20]  (value not drawn)
FID3  Fiducial  [Fiducial10-20]  (value not drawn)
FID4  Fiducial  [Fiducial10-20]  (value not drawn)
FID5  Fiducial  [Fiducial10-20]  (value not drawn)
FID6  Fiducial  [Fiducial10-20]  (value not drawn)
H1  NY PMS 440 0025 PH  [NY PMS 440 0025 PH]
H2  NY PMS 440 0025 PH  [NY PMS 440 0025 PH]
H3  NY PMS 440 0025 PH  [NY PMS 440 0025 PH]
H4  NY PMS 440 0025 PH  [NY PMS 440 0025 PH]
H5  1902C  [Keystone_1902C]
H6  1902C  [Keystone_1902C]
H7  1902C  [Keystone_1902C]
H8  1902C  [Keystone_1902C]
H9  IML-0636  (mechanical)
H10  IML-0635  (mechanical)
LBL1  Size: 0.65" x 0.20 "  [Label_650x200]
Logo1  Texas Instruments  [TI_Stacked_Overlay_Small]  (no BOM)
Logo2  Pb-Free Symbol  [Pb-Free_Overlay_Small]  (no BOM)
Logo3  FCC disclaimer  [FCC_disclaimer]  (no BOM)
ZZ1  This Assembly Note is for PCB labels only  [AssemblyNoteLabel]  (no BOM)
ZZ2  These assemblies are ESD sensitive, ESD precautions shall be observed.  [AssemblyNote]  (no BOM)
ZZ3  These assemblies must be clean and free from flux and all contaminants. Use of no clean flux is not acceptable.  [AssemblyNote]  (no BOM)
ZZ4  These assemblies must comply with workmanship standards IPC-A-610 Class 2, unless otherwise specified.  [AssemblyNote]  (no BOM)

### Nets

Not connected (* = marked no-connect by the designer): H1 1; H2 1; H3 1; H4 1

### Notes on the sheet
- Fresnel Lenses
- Variant
- Variant/Label Table
- Label Text
- 001
- 002
- ChangeMe!

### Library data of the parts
!PCB = PCB: Manufacturer: Any; PartNumber: TIDA-01069; SymbolCreator: a0412235
FID1-FID6 = Fiducial: Fiducial mark.  There is nothing to buy or mount.; SymbolCreator: codlsc
H1-H4 = NY PMS 440 0025 PH: Machine Screw, Round, #4-40 x 1/4, Nylon, Philips panhead; Manufacturer: B&F Fastener Supply; CompType: Hardware; SymbolCreator: codlsc; U/M: EA
H5-H8 = 1902C: Standoff, Hex, 0.5"L #4-40 Nylon; Manufacturer: Keystone; CompType: Hardware
H9 = IML-0636: Fresnel Lens; Manufacturer: MuRata; SymbolCreator: Altium
H10 = IML-0635: Fresnel Lens; Manufacturer: MuRata; SymbolCreator: Altium
LBL1 = THT-14-423-10: Thermal Transfer Printable Labels, 0.650" W x 0.200" H - 10,000 per roll; Manufacturer: Brady; SymbolCreator: a0412235; CompType: Label
Logo1 = TI_Logo: Texas Instrument Corporate Signature; SymbolCreator: codlsc
Logo2 = Pb-Free: SymbolCreator: a0412235
Logo3 = FCC_disclaimer: SymbolCreator: codlsc
ZZ1 = AssemblyNoteLabel: SymbolCreator: a0412235
ZZ2-ZZ4 = AssemblyNote: SymbolCreator: codlsc

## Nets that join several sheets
GND: PIR Motion Detector 2.0_BlankSheet (35 pins), PIR Motion Detector 2.0_PowerSheet (40 pins)
VCC1A: PIR Motion Detector 2.0_BlankSheet (PIR1.1 R3.2 U1.5), PIR Motion Detector 2.0_PowerSheet (5 pins)
VCC1B: PIR Motion Detector 2.0_BlankSheet (U7.1 U7.8), PIR Motion Detector 2.0_PowerSheet (C24.1 R28.2)
VCC2A: PIR Motion Detector 2.0_BlankSheet (PIR2.1 R9.2 U2.5), PIR Motion Detector 2.0_PowerSheet (5 pins)
VCC2B: PIR Motion Detector 2.0_BlankSheet (U8.8), PIR Motion Detector 2.0_PowerSheet (C29.1 R30.2)
VCC3: PIR Motion Detector 2.0_BlankSheet (5 pins), PIR Motion Detector 2.0_PowerSheet (5 pins)
ADC1ALERT: PIR Motion Detector 2.0_BlankSheet (U7.2), PIR Motion Detector 2.0_PowerSheet (J11.17 R35.1 U16.1)
ADC2ALERT: PIR Motion Detector 2.0_BlankSheet (U8.2), PIR Motion Detector 2.0_PowerSheet (J11.19 R36.1 U17.1)
PIR_OUT_HI: PIR Motion Detector 2.0_BlankSheet (U4.4 U21.1), PIR Motion Detector 2.0_PowerSheet (J10.9)
PIR_OUT_LO: PIR Motion Detector 2.0_BlankSheet (U5.4 U22.1), PIR Motion Detector 2.0_PowerSheet (J10.15)
SCL: PIR Motion Detector 2.0_BlankSheet (U7.10 U8.10), PIR Motion Detector 2.0_PowerSheet (5 pins)
SDA: PIR Motion Detector 2.0_BlankSheet (U7.9 U8.9), PIR Motion Detector 2.0_PowerSheet (5 pins)

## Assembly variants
001: not fitted C9 C14 C16 FID1 FID2 FID3 FID4 FID5 FID6 J1 J2 J3 J4 J5 R40 R41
